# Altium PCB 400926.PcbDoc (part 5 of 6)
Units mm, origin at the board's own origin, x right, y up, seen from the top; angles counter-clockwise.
Board outline 148.5 x 63.5 mm, 4 copper layers (Top Layer, Mid-Layer 1, Mid-Layer 2, Bottom Layer), stack 1.514 mm thick; 311 components, 281 nets, 1495 pads, 2232 vias.
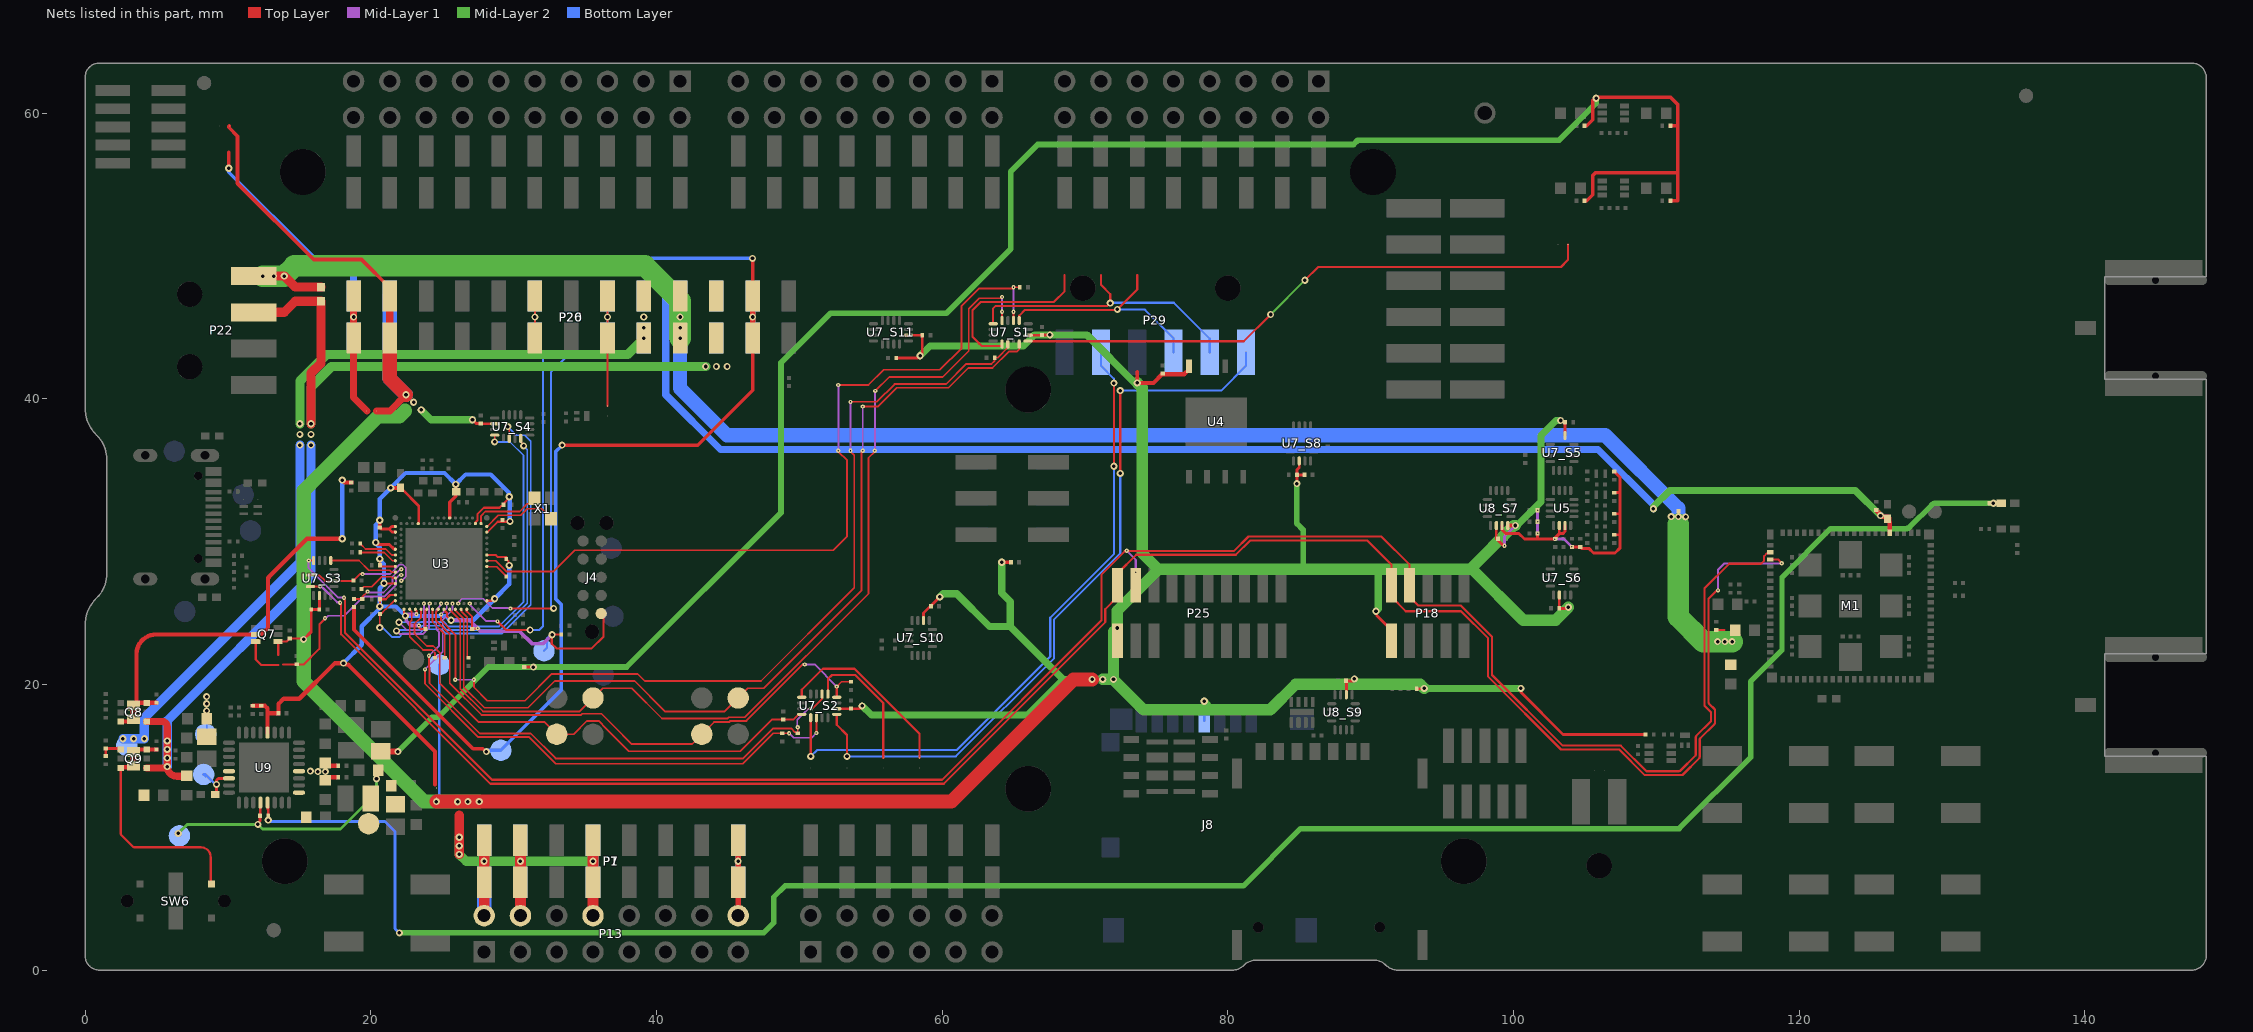
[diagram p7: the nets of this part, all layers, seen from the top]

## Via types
v1: diameter 0.5, hole 0.25, Top Layer to Bottom Layer, tented both sides, 1704 vias
v2: diameter 0.3, hole 0.1, Top Layer to Mid-Layer 1, tented top, 426 vias
v3: diameter 0.3, hole 0.1, Top Layer to Mid-Layer 1, tented both sides, 93 vias
v4: diameter 0.61, hole 0.305, Top Layer to Bottom Layer, tented both sides, 9 vias

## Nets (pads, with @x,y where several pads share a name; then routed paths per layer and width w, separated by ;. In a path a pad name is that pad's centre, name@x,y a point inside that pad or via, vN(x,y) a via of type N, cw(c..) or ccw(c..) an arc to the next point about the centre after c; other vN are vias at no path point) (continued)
SWD1_SEL: P20.8 P26.8 SB17.2 U3.AK22 | length 39.5
  Top Layer w0.15: v2(29.777,25.31) 32.786,25.31 v1(32.8,25.324) ; SB17.2@36.576,39.485 SB17.2@36.576,39.497 P20.8@36.576,44.255 v1(36.576,45.72) P20.8@36.576,47.185
  Mid-Layer 1 w0.125: v2(26.125,25.658) 26.125,25.705 26.187,25.768 26.187,25.798 26.385,25.995 27.865,25.995 28.513,25.347 29.616,25.347
  Bottom Layer w0.15: v1(32.8,25.324) 32.612,25.511 32.612,41.858 33.715,42.96 35.866,42.96 36.576,43.67 P26.8@36.576,44.255 v1(36.576,45.72) P26.8@36.576,47.185
SWD1_SWO: P20.6 P26.6 U3.AK26 | length 32.8
  Top Layer w0.15: v2(28.875,24.409) 29.476,23.808 v1@31,23.808 ; P20.6@31.496,43.612 v1(31.496,45.72) P20.6@31.496,47.185
  Mid-Layer 1 w0.125: v2(26.925,25.658) 26.925,25.581 28.06,24.446 28.715,24.446 28.718,24.442 28.842,24.442 v2(28.875,24.409)
  Bottom Layer w0.15: v1(31.159,23.808) 31.795,23.808 32.062,24.075 32.062,43.103 31.496,43.67 P26.6@31.496,44.255 v1(31.496,45.72) P26.6@31.496,47.185
SWD3_CLK: R20.1 U3.R1 | length 2.7
  Top Layer w0.125: R20.1@19.26,29.258 19.26,29.243 19.27,29.233 20.946,29.233 21.521,28.658 U3.R1@21.725,28.658
SWD3_IO: R19.1 U3.N1 | length 2.8
  Top Layer w0.125: R19.1@19.26,29.858 19.26,29.843 19.333,29.77 19.348,29.77 19.635,29.483 21.05,29.483 21.475,29.058 U3.N1@21.725,29.058
SWD3_RESET: R22.1 U3.AA1 | length 2.8
  Top Layer w0.125: R22.1@19.36,26.683 19.514,26.836 20.056,26.836 20.758,27.539 21.444,27.539 21.525,27.458 U3.AA1@21.725,27.458
SWD3_SWO: U3.W1 U7_S3.5 | length 4.9
  Top Layer w0.125: U7_S3.5@17.2,28.674 19.174,28.674 19.852,27.996 21.341,27.996 21.479,27.858 U3.W1@21.725,27.858
SWD_CTRL: R24.2 U3.AB2 U7_S3.2 U7_S3.10 | length 8.5
  Top Layer w0.125: U7_S3.10@15.775,27.649 16.4,27.649 16.8,27.249 U7_S3.2@17.425,27.249 18.765,27.249 19.24,27.724 v2(19.425,27.724)
  Mid-Layer 1 w0.125: v2(19.425,27.724) 21.349,27.724 21.996,28.37 22.254,28.37 22.45,28.175 22.45,27.541 22.167,27.258 v2(22.125,27.258)
SWDCLK: M1.3 P18.4 P25.4 U7_S3.8 | length 144.5
  Top Layer w0.15: v2(15.65,28.674) U7_S3.8@16,28.674 ; v2(18.125,26.074) 18.154,26.045 18.154,25.915 18.2,25.869 18.2,23.614 28.49,13.324 60,13.324 71.15,24.474 71.15,27.677 72.792,29.319 72.898,29.319 v2(72.927,29.347) 80.446,29.347 81.45,30.352 90.752,30.352 92.73,28.374 P18.4@92.73,26.949 92.73,26.129 93.335,25.524 96.317,25.524 98.5,23.341 98.5,20.661 103.447,15.714 107.524,15.714 109.314,13.924 111.588,13.924 ccw(c111.588,14.074) 111.694,13.968 112.721,14.995 ccw(c112.615,15.101) 112.765,15.101 112.765,16.302 cw(c112.915,16.302) 112.809,16.407 113.797,17.396 ccw(c113.69,17.502) 113.84,17.502 113.84,17.971 ccw(c113.69,17.971) 113.797,18.077 113.419,18.455 cw(c113.525,18.561) 113.375,18.561 113.375,26.725 115.099,28.449 117.333,28.449 117.55,28.667 117.55,28.819 117.55,28.982 117.742,29.174 117.9,29.174 M1.3@117.975,29.249
  Mid-Layer 1 w0.15: v2(15.65,28.674) 15.65,28.144 17.72,26.074 v2(18.125,26.074) ; v2(72.927,29.347) 73.555,28.719 v2(73.555,27.849)
SWDIO: M1.4 P18.2 P25.2 U7_S3.12 | length 142.7
  Top Layer w0.15: U7_S3.12@15.775,26.849 v2@16.375,26.849 ; v2(16.45,26.849) v2@16.375,26.849 ; v2@16.45,26.924 v2@16.375,26.849 ; v2(17.85,25.724) 17.85,25.683 17.925,25.608 17.925,23.501 28.377,13.049 60.114,13.049 71.425,24.36 71.425,25.269 72.285,26.129 P25.2@72.285,26.949 72.285,27.769 73.588,29.072 80.559,29.072 81.564,30.077 89.757,30.077 91.46,28.374 P18.2@91.46,26.949 91.46,26.129 92.465,25.124 96.328,25.124 98.225,23.227 98.225,20.547 103.333,15.439 107.41,15.439 109.2,13.649 111.763,13.649 ccw(c111.763,13.799) 111.869,13.693 112.996,14.82 ccw(c112.89,14.926) 113.04,14.926 113.04,14.994 113.04,16.127 cw(c113.19,16.127) 113.084,16.232 114.072,17.221 ccw(c113.965,17.327) 114.115,17.327 114.115,18.171 ccw(c113.965,18.171) 114.072,18.277 ; 114.072,18.277 113.694,18.655 cw(c113.8,18.761) 113.65,18.761 113.65,25.982 114.217,26.549 114.292,26.549 v3(114.321,26.578) ; M1.4@117.975,28.749 118.528,28.749 v3(118.786,28.49)
  Mid-Layer 1 w0.15: v2(16.45,26.849) 16.556,26.849 17.656,25.749 17.825,25.749 v2(17.85,25.724) ; v3(114.321,26.578) 114.321,28.02 114.763,28.462 118.758,28.462 v3(118.786,28.49)
TGT_SCL: U3.AK12 U7_S4.4 | length 26.2
  Top Layer w0.125: U7_S4.4@30.5,37.224 30.5,36.983 30.7,36.783 v1(30.7,36.699)
  Mid-Layer 1 w0.125: v1(21.8,23.749) 22.012,23.536 23.665,23.536 24.075,23.946 24.075,25.608 v2(24.125,25.658)
  Bottom Layer w0.125: v1(21.8,23.749) 21.857,23.806 23.311,23.806 23.617,24.111 25.034,24.111 25.34,23.806 29.078,23.806 30.95,25.678 30.95,36.438 30.7,36.688 v1(30.7,36.699)
TGT_SDA: U3.AK10 U7_S4.16 | length 26.5
  Top Layer w0.125: v1(28.675,36.974) U7_S4.16@28.675,37.449
  Mid-Layer 1 w0.125: v1(21.975,24.349) 22.537,23.786 23.541,23.786 23.725,23.97 v2(23.725,25.658)
  Bottom Layer w0.125: v1(21.975,24.349) 23.501,24.349 23.514,24.361 25.138,24.361 25.444,24.056 28.974,24.056 30.7,25.781 30.7,36.024 29.75,36.974 v1(28.675,36.974)
TGT_TWI_CTRL: R31.1 U3.AJ1 U7_S4.2 | length 28.8
  Top Layer w0.125: v1(20.625,23.974) 20.635,23.984 20.635,24.849 21.062,25.277 21.643,25.858 U3.AJ1@21.725,25.858 ; v1(29.6,38.049) 29.7,37.949 U7_S4.2@29.7,37.224
  Bottom Layer w0.125: v1(20.625,23.974) 20.836,23.974 21.498,23.311 21.981,23.311 22.225,23.556 23.415,23.556 23.721,23.861 24.931,23.861 25.237,23.556 29.182,23.556 31.2,25.574 31.2,37.024 30.775,37.449 30.2,37.449 v1(29.6,38.049)
UART1.CTS: P29.6 SB6.2 U7_S2.13 | length 51.7
  Top Layer w0.15: U7_S2.13@52.625,17.899 52.625,17.169 53.34,16.454 v1(53.34,14.961) ; v1(72.475,34.774) v1(72.475,40.565)
  Bottom Layer w0.15: v1(53.34,14.961) 60.967,14.961 67.842,21.836 67.842,24.553 72.475,29.185 v1(72.475,34.774) ; v1(72.475,40.565) 79.541,40.565 81.28,42.304 P29.6@81.28,43.249
UART1.RTS: P29.2 SB5.2 U7_S2.9 | length 46.2
  Top Layer w0.15: SB5.2@50.8,14.837 SB5.2@50.8,14.849 v1(50.8,14.961) U7_S2.9@50.8,17.674 U7_S2.9@50.8,17.874 ; v1(72.025,35.274) v1(72.025,41.099)
  Bottom Layer w0.15: v1(50.8,14.961) 51.25,15.411 61.028,15.411 67.567,21.95 67.567,24.666 72.025,29.124 v1(72.025,35.274) ; P29.2@71.12,43.249 71.12,42.304 72.025,41.399 v1(72.025,41.099)
UART1.RXD: P29.4 SB3.2 U7_S1.1 | length 16.1
  Top Layer w0.15: U7_S1.1@65.4,45.474 65.4,45.817 65.807,46.224 72.24,46.224 v1(72.268,46.252) 73.66,47.644 SB3.2@73.66,48.649 SB3.2@73.66,48.661
  Bottom Layer w0.15: v1(72.268,46.252) 74.172,46.252 74.221,46.203
  Bottom Layer w0.152: 74.221,46.203 76.2,44.224 P29.4@76.2,43.249
UART1.TXD: P29.5 SB4.2 U7_S1.5 | length 20.6
  Top Layer w0.15: U7_S1.5@63.575,45.249 63.575,46.324 63.75,46.499 71.575,46.499 v1(71.775,46.699) 71.775,47.324 71.12,47.979 SB4.2@71.12,48.661
  Bottom Layer w0.15: v1(71.775,46.699) 71.8,46.724 76.225,46.724 78.74,44.209 P29.5@78.74,43.249
UART2.CTS: SB10.2 U7_S2.5 | length 13
  Top Layer w0.15: U7_S2.5@50.175,19.099 50.175,19.622 51.652,21.099 53.864,21.099 58.42,16.543 SB10.2@58.42,14.849 SB10.2@58.42,14.837
UART2.RTS: SB9.2 U7_S2.1 | length 9.7
  Top Layer w0.15: U7_S2.1@52,19.324 52,20.374 52.287,20.661 53.912,20.661 55.88,18.694 SB9.2@55.88,14.849 SB9.2@55.88,14.837
UART2.RXD: SB7.2 U7_S1.9 | length 12.4
  Top Layer w0.15: U7_S1.9@64.2,43.824 64.2,43.739 64.162,43.701 62.755,43.701 62.55,43.906 62.55,43.913 62.125,44.338 62.125,46.193 62.706,46.774 67.825,46.774 68.58,47.529 SB7.2@68.58,48.649 SB7.2@68.58,48.661
UART2.TXD: SB8.2 U7_S1.13 | length 41.2
  Top Layer w0.15: U7_S1.13@66.025,44.049 66.05,44.024 81.125,44.024 v1(83,45.899) ; v1(85.4,48.299) 86.325,49.224 103.325,49.224 103.81,49.709 SB8.2@103.81,50.8
  Mid-Layer 2 w0.15: v1(83,45.899) v1(85.4,48.299)
USB_DETECT: Q7.3 R74.2 SB29.2 U3.Y2 | length 15.1
  Top Layer w0.15: Q7.3@11.95,22.999 11.95,21.749 12.35,21.349 SB29.2@13.525,21.349 ; 13.878,21.387 R74.2@14.825,21.387 ; R74.2@14.825,21.414 14.84,21.399 15.3,21.399 16.4,22.499 16.4,24.199 16.796,24.595 v2(16.796,24.636)
  Mid-Layer 1 w0.125: v2(16.796,24.636) 16.837,24.636 17.012,24.811 18.157,24.811 19.507,26.161 20.972,26.161 21.775,26.965 21.775,27.432 22.001,27.658 v2(22.125,27.658)
VBUS: Q7.2 Q8.3 Q8.6 R21.1 R78.2 | length 32
  Top Layer w0.3: Q8.3@2.495,17.399 3.225,17.399 ccw(c3.225,17.574) Q8.3@3.4,17.574 ; Q8.6@3.4,18.524 3.59,18.714 Q8.6@4.305,18.714 ; Q8.6@3.6,18.524 3.6,22.132 cw(c4.967,22.132) 4.967,23.499 Q7.2@11.95,23.499 11.975,23.524 12.364,23.524 12.8,23.96 12.8,27.332 cw(c13.1,27.332) 12.888,27.544 15.542,30.199 v1(18,30.199) ; Q8.6@4.305,18.699 Q8.6@4.305,18.714 ; R78.2@5,18.714 Q8.6@4.305,18.714 ; v1(18,34.299) 18.165,34.134 R21.1@18.625,34.134
  Top Layer w0.5: Q8.3@3.4,17.574 Q8.6@3.4,18.524
  Bottom Layer w0.3: v1(18,30.199) v1(18,34.299)
VBUSOUT: C64.2 TP25.1 U9.22 | length 3.3
  Top Layer w0.2: C64.2@9.1,12.299 ccw(c9.1,12.399) 9.2,12.399 v1(9.2,12.999) 9.2,13.199 cw(c9.425,13.199) 9.425,13.424 U9.22@10.075,13.424
  Bottom Layer w0.15: TP25.1@8.3,13.699 TP25.1@8.425,13.574
  Bottom Layer w0.2: TP25.1@8.3,13.699 8.419,13.699 9.119,12.999 v1(9.2,12.999)
VCOM0_CTRL: R13.1 U3.R31 U7_S1.2 | length 57
  Top Layer w0.125: U3.R31@28.125,28.658 28.754,28.658 29.516,27.895 32.771,27.895 34.275,29.399 52.375,29.399 53.35,30.374 53.35,35.684 52.737,36.297 v2(52.737,36.349) ; v2(52.737,40.961) 54.841,40.961 55.904,42.024 59.839,42.024 61.362,43.547 61.362,46.508 62.566,47.711 64.912,47.711 v2(65,47.799) R13.1@65.44,47.799 ; U7_S1.2@65,45.474 v2(65,46.099)
  Mid-Layer 1 w0.125: v2(52.737,36.349) v2(52.737,40.961) ; v2(65,46.099) v2(65,47.799)
VCOM0_CTS: R86.1 TP5.1 U3.AL9 U7_S2.8 | length 35.9
  Top Layer w0.125: U3.AL9@23.525,25.258 23.525,24.716 23.062,24.253 23.062,23.547 23.923,22.686 24.366,22.686 24.838,22.215 24.838,20.071 27.547,17.361 32.167,17.361 32.822,16.707 32.822,16.311 TP5.1@33.02,16.509 34.201,16.509 35.139,17.446 35.948,17.446 36.497,16.897 36.497,16.894 38.07,15.321 45.858,15.321 48.076,17.539 R86.1@48.875,17.539 49.59,17.539 49.95,17.899 U7_S2.8@50.175,17.899
VCOM0_HWFC: R18.2 U3.AK20 U7_S2.10 | length 38.4
  Top Layer w0.125: v2(23.8,21.049) 23.8,20.048 27.537,16.311 31.095,16.311 32.957,14.449 46.046,14.449 48.181,16.584 v2(49.285,16.584) ; v2(51.2,16.599) U7_S2.10@51.2,17.674
  Mid-Layer 1 w0.125: v2(23.8,21.049) 25.037,22.286 25.037,24.534 25.725,25.222 v2(25.725,25.658) ; v2(49.285,16.584) 49.607,16.261 50.862,16.261 v2(51.2,16.599)
VCOM0_RTS: R15.1 U3.AL5 | length 4.6
  Top Layer w0.125: U3.AL5@22.725,25.258 22.725,25.234 22.862,25.096 22.862,24.486 22.725,24.349 22.725,23.35 23.663,22.411 24.287,22.411 24.5,22.199 R15.1@24.5,21.868
VCOM0_RXD: TP4.1 U3.AL19 U7_S1.4 | length 69.7
  Top Layer w0.125: U3.AL19@25.525,25.216 25.542,25.216 26.262,24.496 26.262,20.464 26.262,20.184 26.262,19.707 27.858,18.111 34.622,18.111 TP4.1@35.56,19.049 36.247,19.736 38.262,19.736 40.387,17.611 44.991,17.611 45.076,17.696 46.194,17.696 54.85,26.353 54.85,35.859 55.287,36.297 v2(55.287,36.349) ; v2(55.325,40.549) 56.3,41.524 60.046,41.524 61.862,43.34 61.862,46.301 62.598,47.036 64.087,47.036 v2@64.175,47.124 ; U7_S1.4@64.2,45.474 v2(64.2,46.099)
  Top Layer w0.15: U3.AL19@25.525,25.216 U3.AL19@25.525,25.258
  Mid-Layer 1 w0.125: v2(55.287,36.349) 55.306,36.368 55.306,40.53 v2(55.325,40.549) ; v2@64.175,47.124 64.2,47.099 v2(64.2,46.099)
  other v2: 64.2,47.124
VCOM0_TXD: R11.1 U3.U31 | length 1.7
  Top Layer w0.125: U3.U31@28.125,28.258 28.144,28.239 28.819,28.239 R11.1@29.5,27.558
VCOM1_CTRL: R14.2 U3.AK18 U7_S1.10 | length 64.5
  Top Layer w0.125: v2@24.925,24.924 v2(24.925,24.899) 24.925,24.474 25.925,23.474 v2(25.925,20.324) ; v2(27.225,20.324) 27.225,19.805 28.169,18.861 30.8,18.861 32.675,20.736 38.677,20.736 39.177,20.236 47.32,20.236 53.85,26.767 53.85,36.034 53.587,36.297 v2(53.587,36.349) ; v2@53.587,39.749 53.625,39.786 55.437,39.786 56.675,41.024 60.275,41.024 61.687,42.436 63.459,42.436 63.661,42.638 63.661,42.85 R14.2@63.685,42.874 63.886,42.874 64.6,43.588 U7_S1.10@64.6,43.824
  Mid-Layer 1 w0.125: v2@24.925,24.924 25.325,25.324 v2(25.325,25.658) ; v2(25.925,20.324) v2(27.225,20.324) ; v2(53.587,36.349) v2(53.587,39.774)
VCOM1_CTS: R85.1 TP9.1 U3.AL15 U7_S2.16 | length 39.4
  Top Layer w0.125: U3.AL15@24.725,25.258 24.725,25.234 24.575,25.084 24.575,24.47 25.537,23.508 25.537,20.078 27.754,17.861 34.726,17.861 34.811,17.946 36.152,17.946 36.155,17.946 36.997,17.104 36.997,17.101 38.277,15.821 42.492,15.821 TP9.1@43.18,16.509 44.032,17.361 45.095,17.361 45.18,17.446 46.297,17.446 50.25,21.399 v2(50.375,21.399) ; v2(52.625,19.849) 52.96,20.184 R85.1@53.625,20.184
  Top Layer w0.15: U7_S2.16@52.625,19.099 v2(52.625,19.849)
  Mid-Layer 1 w0.125: v2(50.375,21.399) 51.075,21.399 v2(52.625,19.849)
VCOM1_HWFC: R17.1 U3.AK16 U7_S2.2 | length 38.7
  Top Layer w0.125: v2(24.075,22.003) 24.075,21.216 24.112,21.178 24.112,20.089 27.64,16.561 31.198,16.561 32.938,14.821 46.065,14.821 48.165,16.921 49.425,16.921 49.69,16.656 49.827,16.656 R17.1@49.9,16.584 v2(49.9,16.999) ; v2(50.8,18.299) 50.9,18.299 51.6,18.999 U7_S2.2@51.6,19.324
  Mid-Layer 1 w0.125: v2(24.075,22.003) 24.787,22.715 24.787,23.657 24.587,23.857 24.587,25.236 24.853,25.502 24.853,25.539 24.925,25.611 v2(24.925,25.658) ; v2(49.9,16.999) 49.862,17.036 49.862,17.539 50.623,18.299 v2(50.8,18.299)
VCOM1_RTS: R16.1 U3.AL13 | length 3.7
  Top Layer w0.125: U3.AL13@24.325,25.258 24.325,24.367 25.175,23.517 R16.1@25.175,21.868
VCOM1_RXD: TP8.1 U3.AL21 U7_S1.12 | length 65.2
  Top Layer w0.125: U3.AL21@25.925,25.234 25.925,25.187 25.976,25.137 ; 25.976,25.136 26.512,24.599 26.512,20.567 26.512,20.081 26.512,19.81 27.961,18.361 31.007,18.361 32.882,20.236 38.47,20.236 40.595,18.111 44.782,18.111 TP8.1@45.72,19.049 46.407,19.736 47.527,19.736 54.35,26.56 54.35,36.261 v2(54.437,36.349) ; v2(54.437,39.449) 55.5,39.449 56.825,40.774 60.45,40.774 61.825,42.149 63.525,42.149 64.687,43.311 65.257,43.311 65.4,43.454 U7_S1.12@65.4,43.824
  Mid-Layer 1 w0.125: v2(54.437,36.349) v2(54.437,39.449)
VCOM1_TXD: R12.1 U3.AL23 | length 3.6
  Top Layer w0.125: U3.AL23@26.325,25.258 26.344,25.239 26.344,25.121 26.762,24.703 26.762,21.931 R12.1@26.825,21.868
VDD: C42.2 C52_S1.1 C52_S2.1 C52_S3.1 C52_S4.1 C52_S5.1 C52_S6.1 C52_S8.1 C52_S10.1 C52_S11.1 C53_S7.1 C53_S9.1 J8.4 P18.1 P20.2 P25.1 P26.2 Q7.4 R8.1 R23.2 R35.2 R62.1 R66.1 R69.2 R75.1 SB16.2 SB20.1 SB29.1 SB30.2 SB31.1 SB32.1 SB33.2 TP23.1 U4.8 U7_S1.14 U7_S2.14 U7_S3.14 U7_S4.14 U7_S5.14 U7_S6.14 U7_S8.14 U7_S10.14 U7_S11.14 U8_S7.14 U8_S7.16 U8_S9.14 | length 344.9
  Top Layer w0.15: SB29.1@13.525,22.049 13.525,22.974 Q7.4@13.5,22.999 14.11,22.999 R75.1@14.325,23.214 15.235,23.214 v1(15.3,23.149)
  Top Layer w0.2: v1(15.3,23.149) 15.835,23.684 C52_S3.1@15.835,25.249 16.335,25.249 16.4,25.314 U7_S3.14@16.4,26.224 ; v1(27.125,38.524) 27.385,38.264 C52_S4.1@27.7,38.264 27.715,38.249 U7_S4.14@28.675,38.249 ; U7_S2.14@52.625,18.299 54.2,18.299 v1(54.4,18.499) ; R66.1@56.785,42.849 58.3,42.849 v1(58.457,43.006) 58.615,43.164 C52_S11.1@58.615,44.449 U7_S11.14@57.643,44.449 ; U7_S10.14@58.7,24.474 58.7,24.992 v1(59.832,26.124) ; U7_S1.14@66.025,44.449 66.985,44.449 C52_S1.1@67,44.464 67.54,44.464 v1(67.55,44.474) ; v1(84.838,34.061) C52_S8.1@84.838,34.67 ; U7_S8.14@85,35.649 85,35.192 84.838,35.03 C52_S8.1@84.838,34.67 ; R35.2@85.368,34.67 C52_S8.1@84.838,34.67 ; U8_S9.14@88.3,19.274 88.3,20.234 v1@88.86,20.234 ; v1(90.375,25.124) 90.432,25.067 90.432,24.817 91.46,23.789 P18.1@91.46,23.049 ; R62.1@93.235,19.699 v1@93.752,19.699 ; U8_S7.14@98.8,31.124 98.8,30.224 99.325,29.699 v2(99.375,29.699) v2@99.4,29.699 ; v1(100.525,19.717) 100.525,19.449 103.475,16.499 R8.1@109.255,16.499 ; U7_S6.14@103.21,26.258 103.208,26.256 C52_S6.1@103.208,25.333 103.217,25.324 103.775,25.324 v1(103.85,25.399)
  Top Layer w0.22: v1(103.3,38.474) 103.376,38.474 103.452,38.398 103.588,38.398 103.61,38.376 U7_S5.14@103.61,37.433
  Top Layer w0.25: v1(73.66,41.109) SB20.1@73.66,41.854 73.66,41.892
  Top Layer w0.254: SB16.2@10.1,59.094 10.062,59.056 10.062,58.999 10.675,58.386 10.675,55.074 16,49.749 19.35,49.749 21.336,47.763 P20.2@21.336,46.948 ; v1(64.176,28.549) R69.2@64.815,28.549 ; U8_S7.16@99.6,31.124 v1(100.137,31.124)
  Top Layer w0.3: v1(73.66,41.109) 74.795,41.109 75.41,41.724 76.95,41.724 77.282,42.056 U4.8@77.282,42.269
  Top Layer w0.5: 20.404,39.147 21.337,39.147 v1(22.47,40.279)
  Top Layer w0.508: P20.2@21.336,44.255 P20.2@21.336,46.948
  Top Layer w1: P20.2@21.336,44.255 21.336,41.413 v1(22.47,40.279) ; v1@24.6,11.799 25.3,11.799 26.078,11.799 60.65,11.799 69.2,20.349 v1(70.5,20.349)
  Mid-Layer 1 w0.2: v2(99.375,29.699) 99.375,30.362 v1(100.137,31.124)
  Mid-Layer 2 w0.4: v1(84.838,34.061) 84.838,31.264 85.282,30.82 85.282,28.049
  Mid-Layer 2 w0.5: v1(23.53,39.219) 24.225,38.524 v1(27.125,38.524) ; v1(54.4,18.499) 55.05,17.849 65.975,17.849 68.475,20.349 ; v1(58.457,43.006) 59.15,43.699 65.7,43.699 66.475,44.474 v1(67.55,44.474) 70.125,44.474 73.49,41.109 v1(73.66,41.109) ; v1(59.832,26.124) 60.057,26.349 61.025,26.349 63.325,24.049 64.775,24.049 ; v1(64.176,28.549) 64.176,26.398 64.775,25.799 64.775,24.049 ; v1(70.5,20.349) 68.475,20.349 ; v1(78.35,18.824) 78.58,18.594 78.58,18.224 ; v1(88.86,20.384) 89.13,20.114 89.13,19.999 ; v1(90.375,25.124) 90.53,25.279 90.53,28.049 ; v1(93.752,19.717) v1(100.525,19.717) ; v1(100.137,31.124) 100.259,31.124 101.925,32.79 101.925,37.43 102.969,38.474 v1(103.3,38.474) ; 64.775,24.049 68.475,20.349
  Mid-Layer 2 w0.8: v1(71.25,20.349) 71.975,20.349 74.1,18.224 78.58,18.224 82.968,18.224 84.743,19.999 89.13,19.999 93.47,19.999 v1(93.752,19.717) ; v1(72,20.349) 72,23.674 v1(72.275,23.949) 72.275,25.169 75.155,28.049 ; v1(73.66,41.109) 74,40.769 74,29.204 75.155,28.049 ; v1(100.137,31.124) 100.025,31.124 96.95,28.049 ; v1(103.85,25.399) 102.95,24.499 100.693,24.499 97.143,28.049 96.95,28.049 ; 75.155,28.049 85.282,28.049 90.53,28.049 96.95,28.049
  Mid-Layer 2 w1: 22.4,39.149 22,38.749 20.5,38.749 15.3,33.549 15.3,20.227 23.728,11.799 v1(26.8,11.799) v1(27.6,11.799)
  Bottom Layer w0.2: v1(24.595,11.798) 24.595,11.864 24.795,12.065 TP23.1@24.795,21.379 ; J8.4@78.35,17.469 v1(78.35,18.824)
  Bottom Layer w1: P26.2@21.336,47.185 P26.2@21.336,44.255 21.336,41.413 v1(22.47,40.279)
  other v1: 26.078,11.784 23,39.749
VDD_1V8: C60.2 C69.2 FB5.1 L7.1 TP21.1 U9.1
VDD_3V0: C72.2 FB6.2 R33.2 R39.2 R40.2 R41.2 R42.2 R87.1 TP27.1 U9.28 | length 156.1
  Top Layer w0.2: v1(12.1,10.199) 12.1,10.28 12.257,10.437 12.257,10.749 12.252,10.754 R87.1@12.252,10.799 12.264,10.811 12.264,11.713 U9.28@12.275,11.724 ; R33.2@30.75,21.214 v1(31.39,21.214)
  Top Layer w0.25: R41.2@104.983,53.867 105.143,53.867 105.556,54.28 105.556,55.631 105.747,55.822 111.496,55.822 ; R39.2@104.983,59.117 105.143,59.117 105.556,59.53 105.556,60.881 ; v1(105.79,61.032) 105.856,61.099 111,61.099 111.499,60.6 111.499,53.867 R42.2@110.983,53.867 ; R40.2@110.983,59.117 111.499,59.117
  Top Layer w0.4: FB6.2@20.7,15.324 20.725,15.299 v1(21.9,15.299)
  Mid-Layer 2 w0.2: v1(6.525,9.574) 7.15,10.199 v1(12.1,10.199) 12.429,9.87 17.871,9.87 20.4,12.399 v1(20.4,13.399)
  Mid-Layer 2 w0.4: v1(21.9,15.299) 24.293,17.692 24.707,17.692 28.228,21.214 v1(31.39,21.214) 37.915,21.214 48.714,32.013 48.714,42.513 52.189,45.988 60.311,45.988 64.8,50.478 64.8,55.899 66.7,57.799 88.8,57.799 89.1,58.099 103.2,58.099 105.8,60.699 105.8,60.999 105.79,61.009 v1(105.79,61.032)
VDD_5V: C54.2 C58.2 P20.11 P22.2 P26.11 Q8.4 Q9.4 R82.2 SB34.2 SB35.1 U9.21 | length 79
  Top Layer w0.5: Q9.4@4.305,14.149 5.65,14.149 v1(5.75,14.249) ; Q8.4@4.305,17.399 5.4,17.399 cw(c5.4,17.049) 5.75,17.049 v1(5.75,16.049) v1(5.75,15.449) v1(5.75,14.849) v1(5.75,14.249) ; C54.2@7.127,13.596 cw(c7.105,13.596) 7.105,13.574 6.425,13.574 cw(c6.425,14.249) v1(5.75,14.249)
  Top Layer w0.65: P22.2@11.811,46.048 13.946,46.048 14.716,46.818 R82.2@16.51,46.818 16.51,42.49 15.819,41.799 v1(15.819,38.249)
  Mid-Layer 2 w0.65: v1(15.819,38.249) 15.819,40.818 17.256,42.255 v1(43.446,42.255)
  Bottom Layer w0.65: v1(5.75,14.249) v1(5.75,14.849) v1(5.75,15.449) v1(5.75,16.049) 5.75,17.449 15.819,27.518 v1(15.819,36.749)
  other v1: 15.819,37.499 44.196,42.255 44.946,42.255
VDD_GNSS: C11.2 L3.1 R87.2 U9.29 | length 148.8
  Top Layer w0.2: U9.29@12.775,11.724 12.775,11.422 12.794,11.403 12.794,11.282 12.827,11.249 12.827,10.849 12.822,10.845 12.828,10.838 v1(12.828,10.503)
  Mid-Layer 2 w0.381: v1@22.032,2.599 47.5,2.599 48.2,3.299 48.2,5.099 49,5.899 81.1,5.899 85.1,9.899 111.6,9.899 116.6,14.899 116.6,20.199 118.8,22.399 118.8,27.499 122.2,30.899 127.467,30.899 ccw(c127.467,31.28) 127.736,31.01 129.299,32.573 cw(c129.568,32.303) 129.568,32.684 v1(133.606,32.684)
  Bottom Layer w0.2: v1(12.828,10.503) 12.831,10.499 ccw(c13.004,10.599) 13.004,10.399 21,10.399 21.7,9.699 21.7,2.899 v1(22,2.599)
VDD_GPIO: C4.1 C5.1 M1.65 P20.1 P26.1 SB31.2 | length 135.5
  Top Layer w0.305: C4.1@125.4,32.184 125.602,31.982 125.602,31.969 125.7,31.871 v1(125.7,31.818) ; v1@125.691,31.799 125.753,31.799 125.805,31.747 126.202,31.747 126.3,31.649 126.3,31.399 126.35,31.349 M1.65@126.35,30.624
  Top Layer w0.5: 18.796,41.889 18.796,40.079 SB31.2@19.728,39.147
  Top Layer w0.508: 18.796,41.889 P20.1@18.796,44.255 P20.1@18.796,47.185
  Mid-Layer 2 w0.5: v1(109.8,32.299) 109.8,32.449 110.937,33.586 123.933,33.586 v1(125.7,31.818)
  Bottom Layer w0.5: P26.1@18.796,47.185 18.796,48.82 19.3,49.324 39.575,49.324 40.65,48.249 40.65,40.274 44.479,36.445 105.929,36.445 109.8,32.574 v1(109.8,32.299)
  Bottom Layer w0.508: P26.1@18.796,44.255 P26.1@18.796,47.185
  other v1: 18.796,45.72
VDD_IMCU: C24.2 C25.2 C26.1 C27.2 C28.1 C31.2 C32.2 C33.2 C34.1 C35.2 C62.1 J4.1 R34.2 R83.2 R84.2 SB32.2 TP12.1 U3.A19 U3.AC1 U3.AG1 U3.AJ31 U3.AL3 U3.AL7 U3.AL11 U3.AL17 U3.AL25 U3.B8 U3.B28 U3.C1 U3.E1 U3.E31 U3.L1 U3.N31 U3.U1 U9.12 | length 105.2
  Top Layer w0.15: v1@20.635,25.458 C26.1@20.635,25.958 ; C25.2@20.635,28.258 U3.U1@21.725,28.258 ; C25.2@20.635,28.333 v1@20.635,28.783 ; C26.1@20.65,25.958 21.05,25.958 21.35,26.258 U3.AG1@21.725,26.258 ; v1@20.925,27.058 U3.AC1@21.725,27.058 ; v1@22.325,24.793 U3.AL3@22.325,25.258 ; v2(23.2,24.921) U3.AL7@23.2,25.183 ; v2(23.375,24.124) 23.375,23.999 23.506,23.868 C27.2@23.827,23.868 23.837,23.879 23.837,25.15 23.925,25.238 U3.AL11@23.925,25.258 ; U3.AL17@25.125,25.216 25.34,25.001 25.34,24.778 v1(25.625,24.493) ; U3.AL25@26.725,25.258 26.725,25.112 27.1,24.737 C31.2@27.1,23.868 27.125,23.893 27.475,23.893 v2(27.5,23.918) ; U3.B28@27.325,31.258 27.325,31.333 27.462,31.47 27.462,31.915 27.918,32.37 29.012,32.37 29.141,32.499 29.23,32.499 29.261,32.53 29.261,32.619 29.7,33.058 v1(29.7,33.133) ; U3.AJ31@28.125,25.858 28.443,25.858 ; U3.N31@28.125,29.058 28.75,29.058 28.9,28.908 C32.2@29.49,28.908 ; U3.E31@28.125,30.658 28.167,30.658 28.892,31.383 v1@29.75,31.383 ; C32.2@29.427,28.845 29.634,28.639 29.634,28.399 v1(29.7,28.333) ; R34.2@33.34,23.499 32.725,23.499 v1(32.7,23.474) 32.675,23.449 32.675,22.849 33,22.524 35.467,22.524 36.3,23.357 36.3,24.794 J4.1@36.135,24.959
  Top Layer w0.187: C35.2@22.175,33.838 22.175,33.666 23.368,32.473 23.368,31.301 U3.B8@23.325,31.258
  Top Layer w0.2: v1(20.35,29.933) 20.5,29.783 21.323,29.783 21.648,29.458 U3.L1@21.725,29.458 ; C24.2@20.625,30.993 20.644,30.958 ccw(c20.809,31.07) 20.809,30.87 21.287,30.87 ; U3.E1@21.725,30.658 21.72,30.663 21.495,30.663 21.287,30.87 ; U3.C1@21.725,31.058 21.475,31.058 21.287,30.87
  Top Layer w0.225: U3.A19@25.525,31.658 25.525,32.753 25.95,33.178 v1(25.95,34.008)
  Top Layer w0.25: C24.2@20.625,30.993 20.619,30.999 20.619,31.491 v1(20.625,31.496)
  Top Layer w0.3: R84.2@11.737,18.501 11.739,18.499 12.599,18.499 12.775,18.323 12.775,17.999 ; U9.12@12.775,16.624 12.775,17.999 ; v1(18.091,21.49) 18.145,21.49 18.245,21.39 18.415,21.39 24.5,15.304 24.5,12.999 ; v1@18.109,21.49 17.491,21.49 15,18.999 13.9,18.999 13.54,18.639 C62.1@13.54,17.974 12.8,17.974 12.775,17.999 ; v1(21.4,33.758) C35.2@22.025,33.758
  Mid-Layer 1 w0.25: v1(22.423,24.793) 22.475,24.741 22.475,24.466 22.817,24.124 v2(23.375,24.124) ; v1@22.527,24.921 v2(23.2,24.921) ; v1(25.625,24.493) 26.925,24.493 v2(27.5,23.918) 27.71,23.708 30.441,23.708 31.291,22.858 32.084,22.858 v1(32.7,23.474)
  Bottom Layer w0.15: TP12.1@32.129,22.352 32.343,22.566 32.343,23.217 32.533,23.407 32.633,23.407 v1(32.7,23.474)
  Bottom Layer w0.3: v1(18.091,21.49) 19.375,22.774 19.375,24.066 20.587,25.278 20.587,25.366 v1@20.625,25.366 ; v1(29.7,28.333) 29.7,27.02 v1(28.675,25.995) 27.173,24.493 v1(25.625,24.493) 25.571,24.493 25.271,24.793 v1(22.423,24.793) 21.758,25.458 v1(20.625,25.458) 20.625,26.733 20.925,27.033 v1(20.925,27.087) 20.925,28.429 20.625,28.729 v1(20.625,28.783) 20.625,29.604 20.35,29.879 v1(20.35,29.933) 20.35,31.167 20.625,31.442 v1(20.625,31.496) 20.625,32.983 v1(21.4,33.758) 22.441,34.799 25.159,34.799 v1(25.95,34.008) 26.641,34.699 28.4,34.699 29.662,33.437 29.662,33.171 v1(29.7,33.133) 29.725,33.108 29.725,31.433 v1(29.75,31.408)
VDD_nRF: C1.1 C2.1 C3.1 FB1.1 P20.10 P22.1 P26.10 R82.1 SB34.1 | length 127.1
  Top Layer w0.125: C1.1@114.19,23.814 114.8,23.814
  Top Layer w0.65: P22.1@11.811,48.588 v1(12.446,48.588) v1(13.196,48.588) v1(13.946,48.588) 14.716,47.818 R82.1@16.51,47.818
  Mid-Layer 2 w1.5: v1(12.446,48.588) v1(13.196,48.588) v1(13.946,48.588) 14.657,49.299 39.2,49.299 41.656,46.843 v1(41.656,45.72) v1(41.656,44.97) v1(41.656,44.22) ; 111.55,31.225 111.55,24.724 113.28,22.994 v1(114.298,22.994) ; v1@114.298,22.991 115.301,22.991 v1(115.305,22.995)
  Bottom Layer w1: P26.10@41.656,44.255 v1(41.656,44.22) 41.656,40.741 44.948,37.449 106.425,37.449 111.55,32.324 v1@111.55,31.849
  other v1: 114.8,22.999 112.053,31.728 111.048,31.744 111.55,31.749
VIN: P1.8 P7.8 P13.16 | length 8.2
  Top Layer w0.381: P13.16@45.72,3.81 P1.8@45.72,6.155 v1(45.72,7.62) P1.8@45.72,9.085
  Bottom Layer w0.381: P7.8@45.72,6.155 v1(45.72,7.62) P7.8@45.72,9.085
VIN:5V: P20.9 P26.9 Q9.1 R79.2 R80.1 TP22.1 | length 56.5
  Top Layer w0.2: R79.2@1.45,14.984 R80.1@1.45,15.514 2.43,15.514 Q9.1@2.495,15.449
  Mid-Layer 2 w0.65: v1(15.044,38.249) 15.044,41.243 16.9,43.099 37.995,43.099 v1(39.116,44.22)
  Bottom Layer w0.65: v1(2.65,16.199) v1(3.4,16.199) v1(4.15,16.199) 4.15,17.649 15.044,28.543 v1(15.044,36.749)
  other v1: 15.044,37.499 39.116,44.97 39.116,45.72
VIN_5V: Q9.3 Q9.6 R81.1 SW6.6 | length 17.3
  Top Layer w0.15: Q9.3@2.495,14.149 2.495,9.566 ccw(c2.645,9.566) 2.539,9.46 3.356,8.643 ccw(c3.462,8.749) 3.462,8.599 8.1,8.599 cw(c8.1,7.899) 8.8,7.899 SW6.6@8.8,6.084
  Top Layer w0.3: Q9.3@2.495,14.149 2.547,14.201 Q9.3@3.182,14.201 ; Q9.3@3.1,14.119 Q9.3@3.182,14.201 ; Q9.3@3.4,14.324 3.305,14.324 Q9.3@3.182,14.201 ; Q9.6@3.4,15.274 3.575,15.449 Q9.6@4.305,15.449 R81.1@5,15.449 ; SW6.6@8.8,6.084 ccw(c8.85,6.084) SW6.6@8.85,6.034
  Top Layer w0.5: Q9.3@3.4,14.324 Q9.6@3.4,15.274
VIO: P1.1 P1.2 P1.4 P7.1 P7.2 P7.4 P13.2 P13.4 P13.8 SB30.1 | length 39.4
  Top Layer w0.65: SB30.1@26.195,10.848 26.2,10.848 v1(26.2,9.299) v1(26.2,8.699) v1(26.2,8.099)
  Top Layer w0.75: P13.2@27.94,3.81 P1.1@27.94,9.085 ; P13.4@30.48,3.81 P1.2@30.48,9.085 ; P13.8@35.56,3.81 v1(35.56,7.62) P1.4@35.56,9.085
  Mid-Layer 2 w0.65: v1(26.2,9.299) v1(26.2,8.699) v1(26.2,8.099) 26.679,7.62 v1(27.94,7.62) v1(30.48,7.62) v1(35.56,7.62)
  Bottom Layer w0.762: P7.1@27.94,6.155 P7.1@27.94,9.085 ; P7.2@30.48,6.155 P7.2@30.48,9.085 ; P7.4@35.56,6.155 P7.4@35.56,9.085
  Bottom Layer w1: P13.2@27.94,3.81 27.94,5.06
VIO_REF: P20.12 P26.12 R64.1 SB15.2 TP16.1 | length 107.1
  Top Layer w0.25: v1(10.062,56.137) 10.062,57.249 ; R64.1@18.825,25.414 18.825,23.838 27.164,15.499 27.832,15.499 28.032,15.299 v1(28.1,15.299) ; v1(33.4,36.749) 42.9,36.749 46.736,40.585 P20.12@46.736,44.255 ; v1@46.7,49.824 46.736,49.788 P20.12@46.736,46.99
  Top Layer w0.381: P20.12@46.736,44.255 v1(46.736,45.72) P20.12@46.736,46.99
  Bottom Layer w0.25: v1(10.062,56.137) 10.062,55.86 16.099,49.824 v1@46.7,49.824 ; v1(28.1,15.299) 28.186,15.385 TP16.1@29.108,15.385 33.35,19.626 33.35,25.574 32.937,25.986 32.937,36.286 v1(33.4,36.749) ; P26.12@46.736,47.185 P26.12@46.736,47.763
  Bottom Layer w0.381: P26.12@46.736,44.255 v1(46.736,45.72) P26.12@46.736,47.185
  other v1: 46.725,49.824
VIO_REF_SENSE: R64.2 R65.2 U3.V2 | length 4.6
  Top Layer w0.125: R64.2@18.825,25.984 R65.2@19.4,25.984 19.4,26.124 v2(19.775,26.499)
  Mid-Layer 1 w0.125: v2(19.775,26.499) 19.838,26.436 20.893,26.436 21.525,27.068 21.525,27.535 21.985,27.995 22.015,27.995 22.078,28.058 v2(22.125,28.058)
VIOEXT: C43.2 R48.2 R49.2 R50.2 R51.2 R52.2 R54.2 R56.2 R58.2 R60.2 U5.14 U5.15 U8_S7.15 | length 20.1
  Top Layer w0.2: U8_S7.15@99.2,31.124 99.204,31.12 99.204,30.831 99.461,30.574 100.375,30.574 100.775,30.174 101.725,30.174 ; v2(101.688,30.571) 101.688,30.211 101.725,30.174 ; U5.14@103.21,31.124 103.21,30.549 ; U5.15@103.61,31.124 103.61,30.695 103.492,30.577 103.238,30.577 103.21,30.549 ; 101.725,30.174 v2(102.906,30.174) C43.2@102.927,30.196 102.927,30.266 103.21,30.549
  Top Layer w0.203: v2(104.095,29.626) R51.2@104.68,29.626 104.777,29.528 105.276,29.528 105.6,29.204 107.118,29.204 107.448,29.533 107.448,31.958 ; R52.2@107.048,30.475 107.443,30.475 ; R54.2@107.048,31.948 107.438,31.948 107.448,31.958 ; R56.2@107.048,33.421 107.437,33.421 ; R60.2@107.048,34.895 107.083,34.895 107.448,34.53 107.448,31.958
  Mid-Layer 1 w0.2: v2(101.688,30.571) v2(101.688,31.384) v2(101.688,32.197)
  Mid-Layer 1 w0.203: v2(102.906,30.174) 103.547,30.174 v2(104.095,29.626)
VSYS: C55.2 C56.2 C65.2 C66.2 C68.2 FB4.2 TP26.1 U9.4 | length 3.6
  Top Layer w0.125: 17.592,13.496 C66.2@17.727,13.496 ; 17.592,14.296 C65.2@17.727,14.296
  Top Layer w0.3: C55.2@16.827,13.296 17.027,13.496 17.592,13.496 ; C56.2@16.827,14.496 17.027,14.296 17.592,14.296
  Bottom Layer w0.125: TP26.1@8.44,16.509 8.513,16.582 v1(8.513,18.144)
  other v1: 16.3,13.899 16.825,13.899 15.773,13.926 8.513,18.644 8.513,19.144
XC1: U3.C31 X1.1 | length 5.3
  Top Layer w0.125: U3.C31@28.125,31.058 28.149,31.058 28.937,31.845 30.512,31.845 30.962,32.295 31.984,32.295 32.625,31.655 X1.1@32.625,31.587
XC2: U3.B30 X1.3 | length 4.6
  Top Layer w0.125: U3.B30@27.725,31.258 27.725,31.806 28.027,32.108 30.421,32.108 30.955,32.642 31.112,32.642 X1.3@31.36,32.89
pads on no net: D5. D5.4 Fid1.0 Fid2.0 Fid3.0 J4.0 J4.6 J4.7 J4.8 J4.9 J5. J5.C6 J6. J6.0 J6.A8 J6.B8 J8.10 M1.26 M1.31 M1.32 M1.33 M1.37 M1.81 M1.82 M1.83 M1.84 M1.85 M1.86 M1.87 M1.88 M1.89 M1.90 M1.91 M1.92 M1.93 M1.94 M1.95 M1.96 M1.97 M1.98 M1.100 M1.102 M1.103 M1.104 P18.7 P18.8 P19.7 P19.8 P19.9 P22.0 P22.3 P25.11 P25.13 P28.3 P28.7 P28.8 P28.9 P28.10 P29.0 P30.0 SW6.0 U1.4 U3. U3.A1 U3.A21 U3.A31 U3.AG31 U3.AK2 U3.AK4 U3.AK6 U3.AL1 U3.AL31 U3.B10 U3.D2 U3.F2 U3.J1 U3.K2 U3.L31 U3.M2 U3.P2 U3.T2 U4.3 U4.7 U6.0 U6.4 U6.5 U8_S7.10 U8_S9.10 U9.7 U9.8 U9.9 U9.10 U9.11 U9.15 U9.18 U9.19 U9.23 U9.24 U9.25 U9.26 U9.27

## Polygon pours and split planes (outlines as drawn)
GND on Top Layer "Top_Layer-GND" (solid, pour order 36): 124.35,18.999 131.6,18.999 131.6,22.599 124.35,22.599
GND on Top Layer "Top_Layer-GND" (solid, remove dead copper, pour order 35): 0,0 0,63.5 152.5,63.5 152.5,0
VDD_nRF on Top Layer "NONET_L-01_P-001" (solid, pour order 33): 114,23.952 115.271,23.952 115.9,23.952 115.9,22.12 cw(c115.609,22.12) 115.815,21.914 115.746,21.845 ccw(c116.082,21.508) 115.606,21.508 115.606,21.004 114.803,21.004 114.8,21.61 ccw(c114.629,21.61) 114.719,21.755 114.114,22.129 cw(c114.24,22.334) 114,22.334
NetC8_2 on Top Layer "VUSB" (solid, pour order 32): 8.9,29.599 10.4,29.599 cw(c10.4,29.399) 10.6,29.399 10.6,28.699 11.6,28.699 11.6,28.099 11,28.099 11,28.299 10,28.299 cw(c10,28.399) 9.9,28.399 9.9,28.899 ccw(c9.8,28.899) 9.8,28.999 9,28.999 cw(c9,29.099) 8.9,29.099
NetC8_2 on Top Layer "VUSB" (solid, pour order 31): 9.1,34.299 11.4,34.299 11.4,33.499 11.4,32.899 11.2,32.899 11.2,33.099 11.2,33.899 9.1,33.899
VDD on Top Layer "NONET_L-01_P-001" (solid, pour order 29): 24.1,11.353 24.1,12.239 cw(c24.16,12.239) 24.16,12.299 25.1,12.299 25.1,11.299 24.154,11.299 cw(c24.154,11.353)
GND on Bottom Layer "Bottom_Layer-GND" (solid, remove dead copper, pour order 18): 0,0 0,63.5 152.25,63.5 152.25,0
GND on Mid-Layer 1 "Mid_Layer_1-GND" (solid, remove dead copper, pour order 22): 0,0 0,63.5 155,63.5 155,0
GND on Mid-Layer 2 "Mid_Layer_2-GND" (solid, remove dead copper, pour order 28): 0,0 0,63.5 155,63.5 155,0

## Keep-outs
Top Layer:
  circle w0.152: c13.97,7.62 r2.4
  circle w0.152: c15.24,55.88 r2.4
  circle w0.152: c66.04,12.7 r2.4
  circle w0.152: c66.04,40.64 r2.4
  circle w0.152: c96.52,7.62 r2.4
  region: 109.775,55.149 110.225,55.149 110.225,54.374 109.775,54.374
  region: 103.75,55.149 104.2,55.149 104.2,54.524 103.75,54.524
  region: 115.475,28.049 116.45,28.049 116.45,27.549 115.475,27.549
  region: 116.675,27.549 117.45,27.549 117.45,26.924 116.675,26.924
  lines w0.152: 90.909,53.597 cw(c90.17,55.88) 91.891,54.207
Bottom Layer:
  circle w1.3: c114.808,48.978 r0.01
  circle w1.3: c113.284,46.609 r0.01
  circle w1.3: c127.127,11.176 r0.01
  circle w1.3: c39.37,16.802 r0.01
  circle w1.3: c22.987,13.964 r0.01
  circle w1.3: c9.869,7.112 r0.01
  circle w1.3: c22.987,13.964 r0.01
  circle w1.3: c34.163,26.543 r0.01
  circle w1.3: c125.476,2.064 r0.01
  circle w1.3: c83.82,14.732 r0.01
  circle w1.3: c86.97,16.149 r0.01
  circle w1.3: c88.804,18.911 r0.01
  circle w1.3: c82.839,19.441 r0.01
  circle w1.3: c53.721,22.078 r0.01
  circle w1.3: c111.379,54.483 r0.01
  circle w0.152: c13.97,7.62 r2.4
  circle w0.152: c15.24,55.88 r2.4
  circle w0.152: c66.04,12.7 r2.4
  circle w0.152: c96.52,7.62 r2.4
  lines w0.152: 67.712,42.362 ccw(c66.04,40.64) 68.297,41.457 ; 90.849,53.578 cw(c90.17,55.88) 91.929,54.247
Keep-Out Layer:
  circle w0.152: c79.1,-0.001 r0.173
  circle w0.152: c78.3,-0.001 r0.173
  circle w0.152: c77.5,-0.001 r0.173
  circle w0.152: c76.7,-0.001 r0.173
  circle w0.152: c75.9,-0.001 r0.173
  circle w0.152: c79.1,63.499 r0.173
  circle w0.152: c78.3,63.499 r0.173
  circle w0.152: c77.5,63.499 r0.173
  circle w0.152: c76.7,63.499 r0.173
  circle w0.152: c75.9,63.499 r0.173
  circle w0.152: c141.6,63.499 r0.173
  circle w0.152: c140.8,63.499 r0.173
  circle w0.152: c140,63.499 r0.173
  circle w0.152: c139.2,63.499 r0.173
  circle w0.152: c138.4,63.499 r0.173
  circle w0.152: c141.6,-0.001 r0.173
  circle w0.152: c140.8,-0.001 r0.173
  circle w0.152: c140,-0.001 r0.173
  circle w0.152: c139.2,-0.001 r0.173
  circle w0.152: c138.4,-0.001 r0.173
  circle w0.152: c16.6,-0.001 r0.173
  circle w0.152: c15.8,-0.001 r0.173
  circle w0.152: c15,-0.001 r0.173
  circle w0.152: c14.2,-0.001 r0.173
  circle w0.152: c13.4,-0.001 r0.173
  circle w0.152: c16.6,63.499 r0.173
  circle w0.152: c15.8,63.499 r0.173
  circle w0.152: c15,63.499 r0.173
  circle w0.152: c14.2,63.499 r0.173
  circle w0.152: c13.4,63.499 r0.173
  circle w0.152: c148.5,51.899 r0.173
  circle w0.152: c148.5,52.699 r0.173
  circle w0.152: c148.5,53.499 r0.173
  circle w0.152: c148.5,54.299 r0.173
  circle w0.152: c148.5,55.099 r0.173
  circle w0.152: c148.5,8.399 r0.173
  circle w0.152: c148.5,9.199 r0.173
  circle w0.152: c148.5,9.999 r0.173
  circle w0.152: c148.5,10.799 r0.173
  circle w0.152: c148.5,11.599 r0.173
  circle w0.152: c0,8.399 r0.173
  circle w0.152: c0,9.199 r0.173
  circle w0.152: c0,9.999 r0.173
  circle w0.152: c0,10.799 r0.173
  circle w0.152: c0,11.599 r0.173
  circle w0.152: c0,51.899 r0.173
  circle w0.152: c0,52.699 r0.173
  circle w0.152: c0,53.499 r0.173
  circle w0.152: c0,54.299 r0.173
  circle w0.152: c0,55.099 r0.173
